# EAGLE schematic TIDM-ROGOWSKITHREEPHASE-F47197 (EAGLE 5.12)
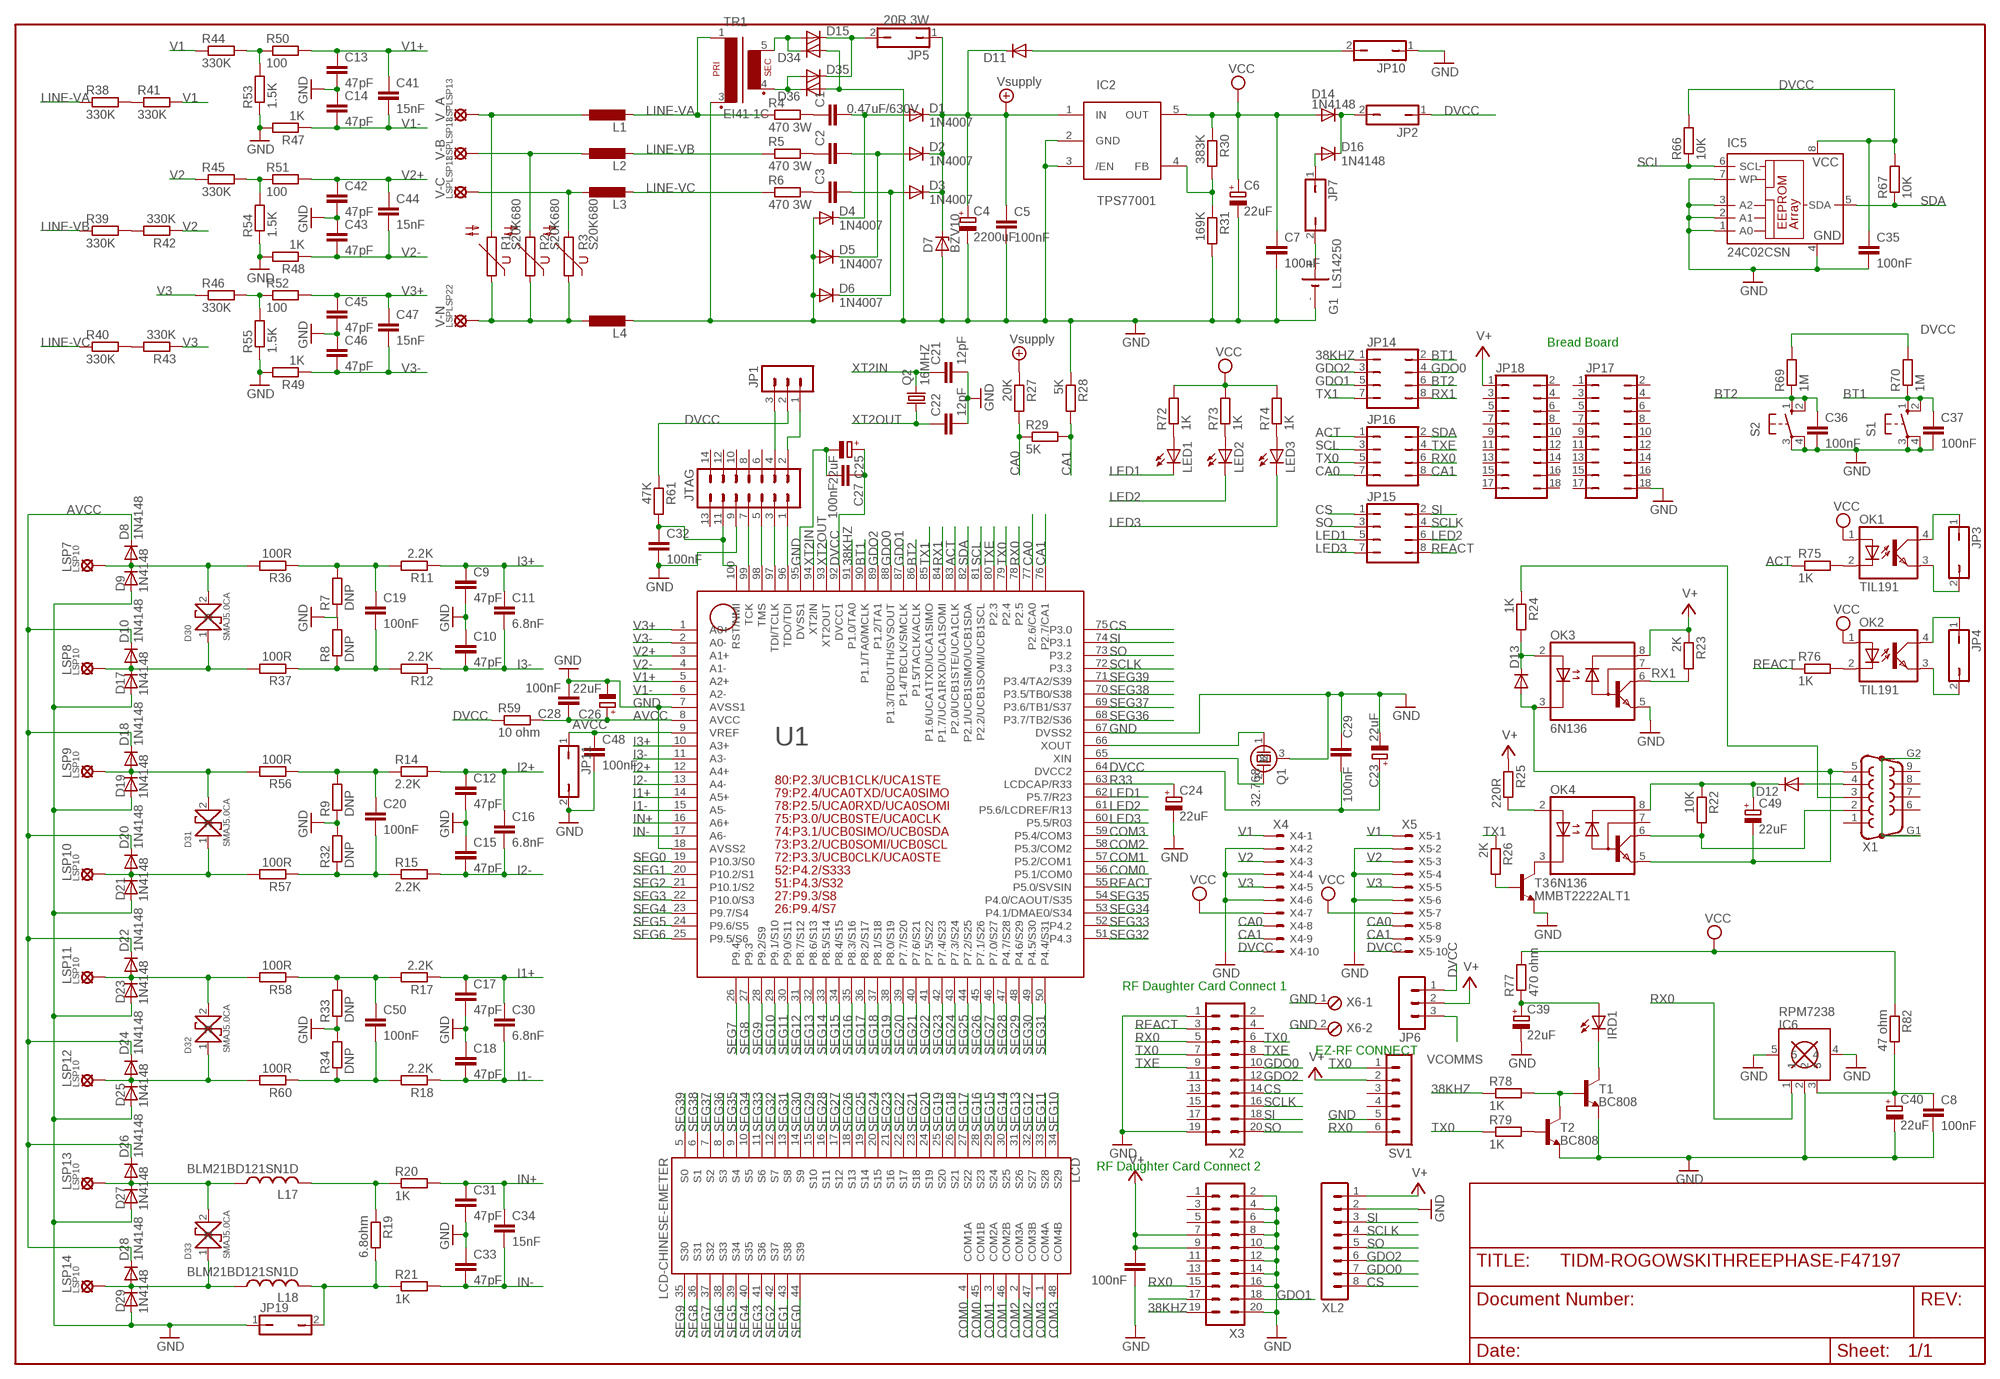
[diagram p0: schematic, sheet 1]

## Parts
C1  0.47uF/630V  C-EU225-062X268  [C225-062X268]
C2  C-EU225-062X268  [C225-062X268]
C3  C-EU225-062X268  [C225-062X268]
C4  2200uF  CPOL-EUE5-13  [E5-13]
C5  100nF  C-EUC0603  [C0603]
C6  22uF  CPOL-EUSMCB  [SMC_B]
C7  100nF  C-EUC0603  [C0603]
C8  100nF  C-EUC0603  [C0603]
C9  47pF  C-EUC0603  [C0603]
C10  47pF  C-EUC0603  [C0603]
C11  6.8nF  C-EUC0603  [C0603]
C12  47pF  C-EUC0603  [C0603]
C13  47pF  C-EUC0603  [C0603]
C14  47pF  C-EUC0603  [C0603]
C15  47pF  C-EUC0603  [C0603]
C16  6.8nF  C-EUC0603  [C0603]
C17  47pF  C-EUC0603  [C0603]
C18  47pF  C-EUC0603  [C0603]
C19  100nF  C-EUC0603  [C0603]
C20  100nF  C-EUC0603  [C0603]
C21  12pF  C-EUC0603  [C0603]
C22  12pF  C-EUC0603  [C0603]
C23  22uF  CPOL-EUSMCB  [SMC_B]
C24  22uF  CPOL-EUSMCB  [SMC_B]
C25  22uF  CPOL-EUSMCB  [SMC_B]
C26  22uF  CPOL-EUSMCB  [SMC_B]
C27  100nF  C-EUC0603  [C0603]
C28  100nF  C-EUC0603  [C0603]
C29  100nF  C-EUC0603  [C0603]
C30  6.8nF  C-EUC0603  [C0603]
C31  47pF  C-EUC0603  [C0603]
C32  100nF  C-EUC0603  [C0603]
C33  47pF  C-EUC0603  [C0603]
C34  15nF  C-EUC0603  [C0603]
C35  100nF  C-EUC0603  [C0603]
C36  100nF  C-EUC0603  [C0603]
C37  100nF  C-EUC0603  [C0603]
C38  100nF  C-EUC0603  [C0603]
C39  22uF  CPOL-EUSMCB  [SMC_B]
C40  22uF  CPOL-EUSMCC  [SMC_C]
C41  15nF  C-EUC0603  [C0603]
C42  47pF  C-EUC0603  [C0603]
C43  47pF  C-EUC0603  [C0603]
C44  15nF  C-EUC0603  [C0603]
C45  47pF  C-EUC0603  [C0603]
C46  47pF  C-EUC0603  [C0603]
C47  15nF  C-EUC0603  [C0603]
C48  100nF  C-EUC0603  [C0603]
C49  22uF  CPOL-EUSMCB  [SMC_B]
C50  100nF  C-EUC0603  [C0603]
D1  1N4007  1N4007DO41-10  [DO41-10]
D2  1N4007  1N4007DO41-10  [DO41-10]
D3  1N4007  1N4007DO41-10  [DO41-10]
D4  1N4007  1N4007DO41-10  [DO41-10]
D5  1N4007  1N4007DO41-10  [DO41-10]
D6  1N4007  1N4007DO41-10  [DO41-10]
D7  BZV10  [DO34Z7]
D8  1N4148  1N4148SOD80C  [SOD80C]
D9  1N4148  1N4148SOD80C  [SOD80C]
D10  1N4148  1N4148SOD80C  [SOD80C]
D11  1N4148SOD80C  [SOD80C]
D12  1N4148SOD80C  [SOD80C]
D13  1N4148SOD80C  [SOD80C]
D14  1N4148  1N4148SOD80C  [SOD80C]
D15  1N4007DO41-10  [DO41-10]
D16  1N4148  1N4148SOD80C  [SOD80C]
D17  1N4148  1N4148SOD80C  [SOD80C]
D18  1N4148  1N4148SOD80C  [SOD80C]
D19  1N4148  1N4148SOD80C  [SOD80C]
D20  1N4148  1N4148SOD80C  [SOD80C]
D21  1N4148  1N4148SOD80C  [SOD80C]
D22  1N4148  1N4148SOD80C  [SOD80C]
D23  1N4148  1N4148SOD80C  [SOD80C]
D24  1N4148  1N4148SOD80C  [SOD80C]
D25  1N4148  1N4148SOD80C  [SOD80C]
D26  1N4148  1N4148SOD80C  [SOD80C]
D27  1N4148  1N4148SOD80C  [SOD80C]
D28  1N4148  1N4148SOD80C  [SOD80C]
D29  1N4148  1N4148SOD80C  [SOD80C]
D30  SMAJ5.0CA  SMAJ  [DO-214]
D31  SMAJ5.0CA  SMAJ  [DO-214]
D32  SMAJ5.0CA  SMAJ  [DO-214]
D33  SMAJ5.0CA  SMAJ  [DO-214]
D34  1N4007DO41-10  [DO41-10]
D35  1N4007DO41-10  [DO41-10]
D36  1N4007DO41-10  [DO41-10]
G1  LS14250  SL-150-1/2AA/PR  [SL-150-1/2AA/PR]
IC2  TPS77001  [SOT23-5]
IC5  24C02CSN  [SO-08]
IC6  RPM7238  RPM7238IR_DET1  [IR_DET1]
IRD1  LED3MM  [LED3MM]
JP1  MA03-1MA03-1  [MA03-1]
JP2  JP1Q  [JP1]
JP3  JP1Q  [JP1]
JP4  JP1Q  [JP1]
JP5  20R 3W  JP1Q  [JP1]
JP6  MA03-1MA03-1  [MA03-1]
JP7  JP1Q  [JP1]
JP10  JP1Q  [JP1]
JP11  JP1Q  [JP1]
JP14  JP4Q  [JP4Q]
JP15  JP4Q  [JP4Q]
JP16  JP4Q  [JP4Q]
JP17  JP9Q  [JP9Q]
JP18  JP9Q  [JP9Q]
JP19  JP1Q  [JP1]
JTAG  MA07-2MA07-2JTAG  [MA07-2JTAG]
L1  L-EU0207/10  [0207/10]
L2  L-EU0207/10  [0207/10]
L3  L-EU0207/10  [0207/10]
L4  L-EUSD8  [SD8]
L17  BLM21BD121SN1D  L-USL2012C  [L2012C]
L18  BLM21BD121SN1D  L-USL2012C  [L2012C]
LCD  LCD-CHINESE-EMETER  [LCD-CHINESE-EMETER]
LED1  LED3MM  [LED3MM]
LED2  LED3MM  [LED3MM]
LED3  LED3MM  [LED3MM]
LSP7  LSP10  [LSP10]
LSP8  LSP10  [LSP10]
LSP9  LSP10  [LSP10]
LSP10  LSP10  [LSP10]
LSP11  LSP10  [LSP10]
LSP12  LSP10  [LSP10]
LSP13  LSP10  [LSP10]
LSP14  LSP10  [LSP10]
OK1  TIL191  [DIL04]
OK2  TIL191  [DIL04]
OK3  6N136  6N135  [DIL08]
OK4  6N136  6N135  [DIL08]
Q1  32.768  CRYSTAL-LSDTC26H-1  [TC26H-1]
Q2  16MHZ  CRYSTALHC49S  [HC49/S]
R1  S20K680  S20K680S20K680-1  [S20K680-1]
R2  S20K680  S20K680S20K680-1  [S20K680-1]
R3  S20K680  S20K680S20K680-1  [S20K680-1]
R4  470 3W  R-EU_RKH208-8  [KH208-8]
R5  470 3W  R-EU_RKH208-8  [KH208-8]
R6  470 3W  R-EU_RKH208-8  [KH208-8]
R7  DNP  R-EU_R0603  [R0603]
R8  DNP  R-EU_R0603  [R0603]
R9  DNP  R-EU_R0603  [R0603]
R11  2.2K  R-EU_R0603  [R0603]
R12  2.2K  R-EU_R0603  [R0603]
R14  2.2K  R-EU_R0603  [R0603]
R15  2.2K  R-EU_R0603  [R0603]
R17  2.2K  R-EU_R0603  [R0603]
R18  2.2K  R-EU_R0603  [R0603]
R19  6.8ohm  R-EU_R0603  [R0603]
R20  1K  R-EU_R0603  [R0603]
R21  1K  R-EU_R0603  [R0603]
R22  10K  R-EU_R0603  [R0603]
R23  2K  R-EU_R0603  [R0603]
R24  1K  R-EU_R0603  [R0603]
R25  220R  R-EU_R0603  [R0603]
R26  2K  R-EU_R0603  [R0603]
R27  20K  R-EU_R0603  [R0603]
R28  5K  R-EU_R0603  [R0603]
R29  5K  R-EU_R0603  [R0603]
R30  383K  R-EU_R0603  [R0603]
R31  169K  R-EU_R0603  [R0603]
R32  DNP  R-EU_R0603  [R0603]
R33  DNP  R-EU_R0603  [R0603]
R34  DNP  R-EU_R0603  [R0603]
R36  100R  R-EU_R0603  [R0603]
R37  100R  R-EU_R0603  [R0603]
R38  330K  R-EU_R0603  [R0603]
R39  330K  R-EU_R0603  [R0603]
R40  330K  R-EU_R0603  [R0603]
R41  330K  R-EU_R0603  [R0603]
R42  330K  R-EU_R0603  [R0603]
R43  330K  R-EU_R0603  [R0603]
R44  330K  R-EU_R0603  [R0603]
R45  330K  R-EU_R0603  [R0603]
R46  330K  R-EU_R0603  [R0603]
R47  1K  R-EU_R0603  [R0603]
R48  1K  R-EU_R0603  [R0603]
R49  1K  R-EU_R0603  [R0603]
R50  100  R-EU_R0603  [R0603]
R51  100  R-EU_R0603  [R0603]
R52  100  R-EU_R0603  [R0603]
R53  1.5K  R-EU_R0603  [R0603]
R54  1.5K  R-EU_R0603  [R0603]
R55  1.5K  R-EU_R0603  [R0603]
R56  100R  R-EU_R0603  [R0603]
R57  100R  R-EU_R0603  [R0603]
R58  100R  R-EU_R0603  [R0603]
R59  10 ohm  R-EU_R0603  [R0603]
R60  100R  R-EU_R0603  [R0603]
R61  47K  R-EU_R0603  [R0603]
R66  10K  R-EU_R0603  [R0603]
R67  10K  R-EU_R0603  [R0603]
R69  1M  R-EU_R0603  [R0603]
R70  1M  R-EU_R0603  [R0603]
R72  1K  R-EU_R0603  [R0603]
R73  1K  R-EU_R0603  [R0603]
R74  1K  R-EU_R0603  [R0603]
R75  1K  R-EU_R0603  [R0603]
R76  1K  R-EU_R0603  [R0603]
R77  470 ohm  R-EU_R0603  [R0603]
R78  1K  R-EU_R0603  [R0603]
R79  1K  R-EU_R0603  [R0603]
R82  47 ohm  R-EU_R0603  [R0603]
S1  10-XX  [B3F-10XX]
S2  10-XX  [B3F-10XX]
SV1  MA06-1MA06-1-1.27  [MA06-1-1.27]
T1  BC808  BC808-NPN-SOT23-BEC  [SOT23-BEC]
T2  BC808  BC808-NPN-SOT23-BEC  [SOT23-BEC]
T3  MMBT2222ALT1  BC808-NPN-SOT23-BEC  [SOT23-BEC]
TR1  EI41-1C  [EI42-1C]
U1  F471X7---PZ100  [PZ100]
V-B  LSPLSP13  [LSP13]
V-C  LSPLSP13  [LSP13]
V-N  LSPLSP22  [LSP22]
V_A  LSPLSP13  [LSP13]
X1  F09HP  [F09HP]
X2  TFM-110-02-SM-D-A-K  [TFM-110-02-SM-D-A-K]
X3  TFM-110-02-SM-D-A-K  [TFM-110-02-SM-D-A-K]
X4  X4  22-23-2101  [22-23-2101]
X5  X5  22-23-2101  [22-23-2101]
X6  MPT22POL200  [2POL200]
XL2  MA08-1MA08-1-2.0  [MA08-1-2.0]

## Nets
38KHZ: JP14.1 R78.1 U1.91(P1.0/TA0) X3.19
+9V: C4.+ C5.1 D1.C D2.C D3.C D7.C D11.C IC2.1(IN) JP5.1 R27.1 ; supply symbol labelled Vsupply
ACT: JP16.1 R75.1 U1.83(P2.0/UCB1STE/UCA1CLK)
AVCC: C26.+ C28.1 D8.C D10.C D18.C D20.C D22.C D24.C D26.C D28.C R59.2 U1.8(AVCC)
BT1: C37.1 JP14.2 R70.1 S1.1(S) S1.2(S1) U1.90(P1.1/TA0/MCLK)
BT2: C36.1 JP14.6 R69.1 S2.1(S) S2.2(S1) U1.86(P1.5/TACLK/ACLK)
CA0: JP16.7 R27.2 R29.1 U1.77(P2.6/CA0) X4.8 X5.8
CA1: JP16.8 R28.2 R29.2 U1.76(P2.7/CA1) X4.9 X5.9
COM0: LCD.4(COM1A) LCD.45(COM1B) U1.56(P5.1/COM0)
COM1: LCD.3(COM2A) LCD.46(COM2B) U1.57(P5.2/COM1)
COM2: LCD.2(COM3A) LCD.47(COM3B) U1.58(P5.3/COM2)
COM3: LCD.1(COM4A) LCD.48(COM4B) U1.59(P5.4/COM3)
CS: JP15.1 U1.75(P3.0) X2.14 XL2.8
DVCC: C23.+ C25.+ C27.1 C29.2 C35.1 IC5.8(VCC) JP1.2 JP2.1 JP6.1 R59.1 R61.1 R66.2 R67.2 R69.2 R70.2 U1.64(DVCC2) U1.92(DVCC1) X4.10 X5.10
GDO0: JP14.4 U1.88(P1.3/TBOUTH/SVSOUT) X2.10 XL2.7
GDO1: JP14.5 U1.87(P1.4/TBCLK/SMCLK) X3.18
GDO2: JP14.3 U1.89(P1.2/TA1) X2.12 XL2.6
GND: C4.- C5.2 C6.- C7.2 C8.2 C9.2 C10.1 C12.2 C13.2 C14.1 C15.1 C17.2 C18.1 C21.2 C22.2 C23.- C24.- C25.- C26.- C27.2 C28.2 C29.1 C31.2 C32.2 C33.1 C35.2 C36.2 C37.2 C38.2 C39.- C40.- C42.2 C43.1 C45.2 C46.1 C48.2 D4.A D5.A D6.A D7.A D9.A D17.A D19.A D21.A D23.A D25.A D27.A D29.A D34.A D36.A G1.- IC2.2(GND) IC2.3(/EN) IC5.1(A0) IC5.2(A1) IC5.3(A2) IC5.4(GND) IC5.7(WP) IC6.2 IC6.4 IC6.5 JP10.1 JP11.2 JP17.18 JP19.1 JTAG.9 L4.2 OK3.5(GND) Q1.3 R7.1 R8.2 R9.1 R28.1 R31.2 R32.2 R33.1 R34.2 R47.2 R48.2 R49.2 R53.1 R54.1 R55.1 S1.3(P) S1.4(P1) S2.3(P) S2.4(P1) SV1.5 T1.E T2.E T3.E TR1.3(P2) U1.7(AVSS1) U1.18(AVSS2) U1.67(DVSS2) U1.95(DVSS1) X2.1 X2.19 X3.2 X3.4 X3.6 X3.8 X3.10 X3.12 X3.14 X3.16 X3.20 X4.2 X4.4 X4.6 X5.2 X5.4 X5.6 X6.1 X6.2 XL2.2
I1+: C17.1 C30.1 R17.1 U1.14(A5+)
I1-: C18.2 C30.2 R18.1 U1.15(A5-)
I2+: C12.1 C16.1 R14.2 U1.12(A4+)
I2-: C15.2 C16.2 R15.2 U1.13(A4-)
I3+: C9.1 C11.1 R11.1 U1.10(A3+)
I3-: C10.2 C11.2 R12.1 U1.11(A3-)
IN+: C31.1 C34.1 R20.2 U1.16(A6+)
IN-: C33.2 C34.2 R21.2 U1.17(A6-)
LED1: JP15.5 LED1.K(C) U1.62(P5.7/R23)
LED2: JP15.6 LED2.K(C) U1.61(P5.6/LCDREF/R13)
LED3: JP15.7 LED3.K(C) U1.60(P5.5/R03)
LINE-VA: L1.2 R4.1 R38.1 TR1.1
LINE-VB: L2.2 R5.1 R39.1
LINE-VC: L3.2 R6.1 R40.1
N$1: L4.1 R1.1 R2.1 R3.1 V-N.1(MP)
N$2: L3.1 R3.2 V-C.MP
N$3: L2.1 R2.2 V-B.MP
N$4: L1.1 R1.2 V_A.MP
N$5: D14.C D16.C JP2.2
N$6: C19.2 R8.1 R12.2 R37.1
N$7: G1.+ JP7.2
N$8: C1.1 R4.2
N$9: C2.1 R5.2
N$10: C3.1 R6.2
N$11: C1.2 D1.A D4.C
N$12: C2.2 D2.A D5.C
N$13: C3.2 D3.A D6.C
N$14: D8.A D9.C D30.2 LSP7.MP R36.2
N$15: D35.A D36.C TR1.4(S3)
N$16: D10.A D17.C D30.1 LSP8.MP R37.2
N$17: D18.A D19.C D31.2 LSP9.MP R56.2
N$18: D20.A D21.C D31.1 LSP10.MP R57.2
N$19: D22.A D23.C D32.2 LSP11.MP R58.2
N$20: D24.A D25.C D32.1 LSP12.MP R60.2
N$21: D26.A D27.C D33.2 L17.1 LSP13.MP
N$22: D28.A D29.C D33.1 L18.1 LSP14.MP
N$23: OK4.2(A) R25.2
N$24: JP19.2 L18.2 R19.2 R21.1
N$25: C19.1 R7.2 R11.2 R36.1
N$26: C20.2 R15.1 R32.1 R57.1
N$27: C50.2 R18.2 R34.1 R60.1
N$28: D16.A JP7.1
N$29: OK4.3(C) T3.C
N$30: R26.2 T3.B
N$31: L17.2 R19.1 R20.1
N$32: R44.2 R50.1 R53.2
N$33: D13.C OK3.2(A) R24.2
N$35: D15.C D35.C JP5.2
N$36: D15.A D34.C TR1.5(S4)
N$37: IC2.4(FB) R30.2 R31.1
N$39: R38.2 R41.1
N$42: C50.1 R17.2 R33.2 R58.1
N$43: C49.- D13.A OK3.3(C) OK4.5(GND) X1.5
N$45: R39.2 R42.2
N$46: JTAG.1 U1.96(TDO/TDI)
N$48: X3.17
N$49: D12.A X1.4
N$50: C49.+ D12.C OK4.8(VCC) R22.1
N$51: R45.2 R51.1 R54.2
N$52: R40.2 R43.2
N$55: JTAG.3 U1.97(TDI/TCLK)
N$56: OK4.6(VO) R22.2 X1.2
N$57: R46.2 R52.1 R55.2
N$60: R24.1 X1.3
N$61: X1.G1 X1.G2
N$62: C20.1 R9.2 R14.1 R56.1
N$104: LED1.A R72.1
N$105: LED2.A R73.1
N$107: LED3.A R74.1
N$109: JP3.1 OK1.4(COL)
N$113: OK2.2(C) R76.2
N$114: OK1.2(C) R75.2
N$116: JTAG.5 U1.98(TMS)
N$117: JP3.2 OK1.3(EMIT)
N$118: JP4.1 OK2.4(COL)
N$119: JP4.2 OK2.3(EMIT)
N$120: R79.2 T2.B
N$121: C39.+ IRD1.A R77.1
N$122: JTAG.7 U1.99(TCK)
N$125: IRD1.K(C) T1.C
N$126: R78.2 T1.B T2.C
N$127: JP1.1 JTAG.2
N$129: C8.1 C40.+ IC6.3 R82.2
N$130: JP1.3 JTAG.4
N$133: D11.A JP10.2
R33: C24.+ U1.63(LCDCAP/R33)
REACT: JP15.8 R76.1 U1.55(P5.0/SVSIN) X2.3
RESET: C32.1 JTAG.11 R61.2 U1.100(RST/NMI)
RX0: IC6.1 JP16.6 SV1.6 U1.78(P2.5) X2.5 X3.15
RX1: JP14.8 OK3.6(VO) R23.2 U1.84(P1.7/UCA1RXD/UCA1SOMI)
SCL: IC5.6(SCL) JP16.3 R66.1 U1.81(P2.2/UCB1SOMI/UCB1SCL)
SCLK: JP15.4 U1.72(P3.3) X2.16 XL2.4
SDA: IC5.5(SDA) JP16.2 R67.1 U1.82(P2.1/UCB1SIMO/UCB1SDA)
SEG0: LCD.44(S39) U1.19(P10.3/S0)
SEG1: LCD.43(S38) U1.20(P10.2/S1)
SEG2: LCD.42(S37) U1.21(P10.1/S2)
SEG3: LCD.41(S36) U1.22(P10.0/S3)
SEG4: LCD.40(S35) U1.23(P9.7/S4)
SEG5: LCD.39(S34) U1.24(P9.6/S5)
SEG6: LCD.38(S33) U1.25(P9.5/S6)
SEG7: LCD.37(S32) U1.26(P9.4)
SEG8: LCD.36(S31) U1.27(P9.3)
SEG9: LCD.35(S30) U1.28(P9.2/S9)
SEG10: LCD.34(S29) U1.29(P9.1/S10)
SEG11: LCD.33(S28) U1.30(P9.0/S11)
SEG12: LCD.32(S27) U1.31(P8.7/S12)
SEG13: LCD.31(S26) U1.32(P8.6/S13)
SEG14: LCD.30(S25) U1.33(P8.5/S14)
SEG15: LCD.29(S24) U1.34(P8.4/S15)
SEG16: LCD.28(S23) U1.35(P8.3/S16)
SEG17: LCD.27(S22) U1.36(P8.2/S17)
SEG18: LCD.26(S21) U1.37(P8.1/S18)
SEG19: LCD.25(S20) U1.38(P8.0/S19)
SEG20: LCD.24(S19) U1.39(P7.7/S20)
SEG21: LCD.23(S18) U1.40(P7.6/S21)
SEG22: LCD.22(S17) U1.41(P7.5/S22)
SEG23: LCD.21(S16) U1.42(P7.4/S23)
SEG24: LCD.20(S15) U1.43(P7.3/S24)
SEG25: LCD.19(S14) U1.44(P7.2/S25)
SEG26: LCD.18(S13) U1.45(P7.1/S26)
SEG27: LCD.17(S12) U1.46(P7.0/S27)
SEG28: LCD.16(S11) U1.47(P4.7/S28)
SEG29: LCD.15(S10) U1.48(P4.6/S29)
SEG30: LCD.14(S9) U1.49(P4.5/S30)
SEG31: LCD.13(S8) U1.50(P4.4/S31)
SEG32: LCD.12(S7) U1.51(P4.3)
SEG33: LCD.11(S6) U1.52(P4.2)
SEG34: LCD.10(S5) U1.53(P4.1/DMAE0/S34)
SEG35: LCD.9(S4) U1.54(P4.0/CAOUT/S35)
SEG36: LCD.8(S3) U1.68(P3.7/TB2/S36)
SEG37: LCD.7(S2) U1.69(P3.6/TB1/S37)
SEG38: LCD.6(S1) U1.70(P3.5/TB0/S38)
SEG39: LCD.5(S0) U1.71(P3.4/TA2/S39)
SI: JP15.2 U1.74(P3.1) X2.18 XL2.3
SO: JP15.3 U1.73(P3.2) X2.20 XL2.5
TX0: JP16.5 R79.1 SV1.1 U1.79(P2.4) X2.6 X2.7
TX1: JP14.7 R26.1 U1.85(P1.6/UCA1TXD/UCA1SIMO)
TXE: JP16.4 U1.80(P2.3) X2.8 X2.9
V1: R41.2 R44.1 X4.1 X5.1
V1+: C13.1 C41.1 R50.2 U1.5(A2+)
V1-: C14.2 C41.2 R47.1 U1.6(A2-)
V2: R42.1 R45.1 X4.3 X5.3
V2+: C42.1 C44.1 R51.2 U1.3(A1+)
V2-: C43.2 C44.2 R48.1 U1.4(A1-)
V3: R43.1 R46.1 X4.5 X5.5
V3+: C45.1 C47.1 R52.2 U1.1(A0+)
V3-: C46.2 C47.2 R49.1 U1.2(A0-)
V+: C38.1 JP6.2 JP18.1 OK3.8(VCC) R23.1 R25.1 SV1.2 X3.7 X3.9 XL2.1
VCC: C6.+ C7.1 D14.A IC2.5(OUT) OK1.1(A) OK2.1(A) R30.1 R72.2 R73.2 R74.2 R77.2 R82.1 X4.7 X5.7
VCOMMS: JP6.3
VREF: C48.1 JP11.1 U1.9(VREF)
XIN: Q1.2 U1.65(XIN)
XOUT: Q1.1 U1.66(XOUT)
XT2IN: C21.1 Q2.2 U1.94(XT2IN)
XT2OUT: C22.1 Q2.1 U1.93(XT2OUT)
Unconnected: JP17.1 JP17.2 JP17.3 JP17.4 JP17.5 JP17.6 JP17.7 JP17.8 JP17.9 JP17.10 JP17.11 JP17.12 JP17.13 JP17.14 JP17.15 JP17.16 JP17.17 JP18.2 JP18.3 JP18.4 JP18.5 JP18.6 JP18.7 JP18.8 JP18.9 JP18.10 JP18.11 JP18.12 JP18.13 JP18.14 JP18.15 JP18.16 JP18.17 JP18.18 JTAG.6 JTAG.8 JTAG.10 JTAG.12 JTAG.13 JTAG.14 OK3.7(VB) OK4.7(VB) SV1.3 SV1.4 X1.1 X1.6 X1.7 X1.8 X1.9 X2.2 X2.4 X2.11 X2.13 X2.15 X2.17 X3.1 X3.3 X3.5 X3.11 X3.13

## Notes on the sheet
- Bread Board
- RF Daughter Card Connect 1
- EZ-RF CONNECT
- RF Daughter Card Connect 2

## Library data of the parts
C1-C3 C5 C7-C22 C27-C38 C41-C48 C50 = ElecMeter:C-EU: CAPACITOR, European symbol
C4 C6 C23-C26 C39 C40 C49 = ElecMeter:CPOL-EU: POLARIZED CAPACITOR, European symbol
D1-D6 D15 D34-D36 = ElecMeter:1N4007
D7 = ElecMeter:BZV10: Z DIODE
D8-D14 D16-D29 = ElecMeter:1N4148: DIODE
D30-D33 = CON1:SMAJ
G1 = ElecMeter:SL-150-1/2AA/PR: LI BATTERY Sonnenschein
IC2 = ElecMeter:TPS77001: VOLTAGE REGULATOR
IC5 = ElecMeter:24C*: Serial EEPROM 1 K/2 K/4 K
IC6 = ElecMeter:RPM7238
IRD1 LED1-LED3 = ElecMeter:LED: LED
JP1 JP6 = ElecMeter:MA03-1: PIN HEADER
JP2-JP5 JP7 JP10 JP11 JP19 = ElecMeter:JP1Q: JUMPER
JP14-JP16 = jumper:JP4Q: JUMPER
JP17 JP18 = jumper:JP9Q: JUMPER
JTAG = ElecMeter:MA07-2: PIN HEADER
L1-L4 = ElecMeter:L-EU: INDUCTOR, European symbol
L17 L18 = ElecMeter:L-US: INDUCTOR, American symbol
LCD = ElecMeter:LCD-CHINESE-EMETER
LSP7-LSP14 = ElecMeter:LSP10: SOLDER PAD
OK1 OK2 = ElecMeter:TIL191: TEXAS INSTRUMENTS OPTO COUPLER
OK3 OK4 = optocoupler:6N135: MOTOROLA OPTO COUPLER
Q1 = ElecMeter:CRYSTAL-LSD
Q2 = crystal:CRYSTAL: CRYSTAL
R1-R3 = ElecMeter:S20K680: VARISTOR
R4-R9 R11 R12 R14 R15 R17-R34 R36-R61 R66 R67 R69 R70 R72-R79 R82 = ElecMeter:R-EU_: RESISTOR, European symbol
S1 S2 = ElecMeter:10-XX: OMRON SWITCH
SV1 = con-lstb:MA06-1: PIN HEADER
T1-T3 = ElecMeter:*-NPN-: NPN Transistror
TR1 = trafo:EI41-1C
U1 = TI_MSP430_v122:F471X7---PZ100
V-B V-C V-N V_A = ElecMeter:LSP
X1 = con-subd:F09HP: SUB-D
X2 X3 = _MSP430:TFM-110-02-SM-D-A-K
X4 X5 = con-molex:22-23-2101: .100" (2.54mm) Center Header - 10 Pin
X6 = con-phoenix-254:MPT2: PHOENIX CONNECTOR
XL2 = con-lstb:MA08-1: PIN HEADER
